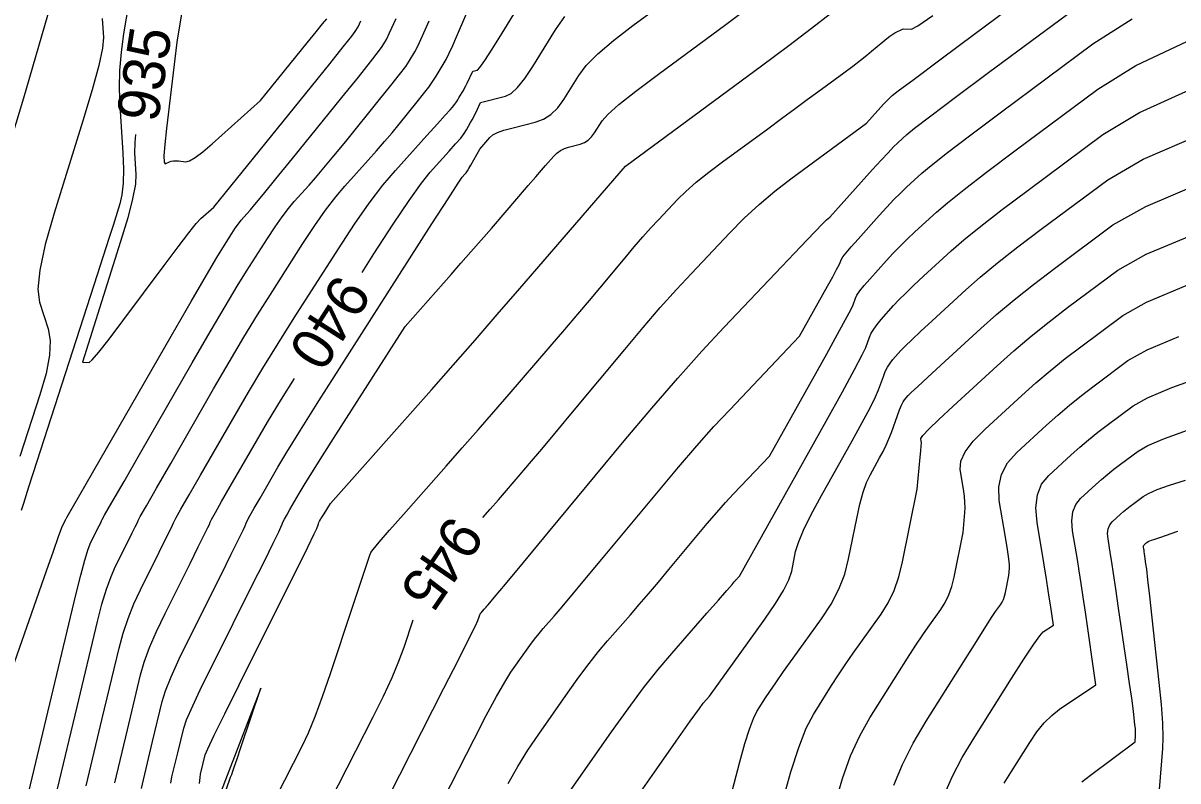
# Model space of a CAD drawing. Extents: x 2175772 to 2185556, y 721391 to 722853.
# Drawn here: x 2178671.4 to 2178748.5, y 721969.8 to 722020.4 of the extents above; entities that cross this region are included whole.
import ezdxf

# ---------------------------------------------------------------- set-up
doc = ezdxf.new("R2010")
doc.units = 0
doc.layers.add('DT_X_Contour_Major', color=7, linetype='Continuous')
doc.layers.add('DT_X_Contour_Minor', color=7, linetype='Continuous')

msp = doc.modelspace()

# ---------------------------------------------------------------- linework, layer by layer
at = {"layer": 'DT_X_Contour_Major'}
for points in [[(2178702.107, 721987.422), (2178702.598, 721987.986), (2178703.143, 721988.614), (2178704.587, 721990.287), (2178705.219, 721991.026), (2178706.032, 721991.989), (2178707.026, 721993.177), (2178708.201, 721994.588), (2178711.576, 721998.65), (2178712.803, 722000.11), (2178713.954, 722001.441), (2178715.029, 722002.644), (2178716.027, 722003.719), (2178718.586, 722006.414), (2178719.561, 722007.398), (2178720.568, 722008.328), (2178721.605, 722009.205), (2178722.674, 722010.029), (2178727.733, 722013.746), (2178728.682, 722014.804), (2178728.869, 722015.012), (2178729.025, 722015.18), (2178729.149, 722015.309), (2178729.241, 722015.399), (2178729.445, 722015.586), (2178729.849, 722015.898), (2178730.906, 722016.693), (2178732.618, 722017.97), (2178734.983, 722019.731), (2178742.163, 722025.071)], [(2178694.037, 722003.786), (2178694.831, 722005.028), (2178696.118, 722007.013), (2178697.173, 722008.58), (2178697.996, 722009.732), (2178698.588, 722010.467), (2178699.857, 722011.873), (2178700.286, 722012.357), (2178700.621, 722012.755), (2178700.863, 722013.067), (2178701.011, 722013.293), (2178701.282, 722013.78), (2178701.379, 722013.959), (2178701.469, 722014.128), (2178701.55, 722014.288), (2178701.623, 722014.438), (2178701.946, 722015.121), (2178703.609, 722015.537), (2178703.991, 722015.729), (2178704.425, 722016.127), (2178704.91, 722016.729), (2178705.446, 722017.538), (2178706.944, 722019.967), (2178707.584, 722020.873)], [(2178678.902, 722012.981), (2178678.852, 722012.463), (2178678.84, 722011.752), (2178678.931, 722010.347), (2178678.892, 722009.671), (2178678.709, 722008.695), (2178678.379, 722007.419), (2178677.905, 722005.843), (2178675.351, 721997.791), (2178675.8, 721997.773), (2178676.013, 721997.944), (2178676.46, 721998.463), (2178677.142, 721999.331), (2178678.059, 722000.548), (2178680.815, 722004.257), (2178681.742, 722005.495), (2178682.458, 722006.427), (2178682.962, 722007.053), (2178683.255, 722007.372), (2178684.125, 722008.149), (2178690.648, 722016.192), (2178691.88, 722017.714), (2178692.779, 722018.834), (2178693.347, 722019.553), (2178693.582, 722019.869), (2178693.768, 722020.177), (2178693.953, 722020.568)], [(2178709.823, 721965.097), (2178713.722, 721970.66), (2178715.012, 721972.497), (2178715.959, 721973.839), (2178716.563, 721974.685), (2178716.824, 721975.034), (2178717.238, 721975.506), (2178720.944, 721980.651), (2178721.651, 721981.678), (2178722.184, 721982.553), (2178722.544, 721983.275), (2178722.73, 721983.845), (2178722.994, 721985.164), (2178723.177, 721985.767), (2178723.526, 721986.589), (2178724.041, 721987.629), (2178724.722, 721988.887), (2178726.762, 721992.534), (2178727.446, 721993.773), (2178727.969, 721994.754), (2178728.331, 721995.478), (2178728.532, 721995.945), (2178728.852, 721996.847), (2178728.982, 721997.17), (2178729.132, 721997.465), (2178729.302, 721997.732), (2178729.492, 721997.969), (2178730.025, 721998.565), (2178730.306, 721998.857), (2178730.747, 721999.287), (2178731.35, 721999.856), (2178732.115, 722000.562), (2178734.368, 722002.631), (2178735.315, 722003.464), (2178736.469, 722004.415), (2178737.829, 722005.481), (2178739.395, 722006.664), (2178743.845, 722009.973), (2178746.198, 722011.338), (2178749.918, 722012.95)], [(2178732.973, 721969.054), (2178733.464, 721970.158), (2178734.126, 721971.404), (2178734.959, 721972.79), (2178737.409, 721976.675), (2178738.231, 721977.963), (2178738.86, 721978.91), (2178739.295, 721979.518), (2178739.537, 721979.786), (2178740.215, 721980.244), (2178740.019, 721981.591), (2178739.96, 721981.976), (2178739.869, 721982.552), (2178739.744, 721983.319), (2178739.586, 721984.278), (2178739.12, 721987.09), (2178739.038, 721988.077), (2178739.139, 721988.929), (2178739.425, 721989.647), (2178739.895, 721990.23), (2178741.393, 721991.606), (2178741.965, 721992.117), (2178742.558, 721992.619), (2178743.172, 721993.113), (2178743.807, 721993.597), (2178745.527, 721994.876), (2178746.495, 721995.422), (2178748.11, 721996.1), (2178750.372, 721996.911)], [(2178677.512, 721969.707), (2178678.361, 721973.251), (2178679.244, 721976.934), (2178679.487, 721977.781), (2178679.841, 721978.744), (2178680.303, 721979.823), (2178680.875, 721981.018), (2178682.546, 721984.359), (2178683.096, 721985.462), (2178683.494, 721986.264), (2178683.741, 721986.767), (2178683.835, 721986.969), (2178683.884, 721987.109), (2178683.982, 721987.297), (2178684.239, 721987.756), (2178684.656, 721988.487), (2178685.231, 721989.489), (2178686.977, 721992.522), (2178687.725, 721993.792), (2178688.66, 721995.325), (2178689.521, 721996.703)], [(2178691.309, 721967.314), (2178694.779, 721974.115), (2178695.466, 721975.5), (2178696.04, 721976.739), (2178696.501, 721977.833), (2178696.85, 721978.783), (2178697.455, 721980.597)]]:
    msp.add_lwpolyline(points, dxfattribs=at)
at = {"layer": 'DT_X_Contour_Minor'}
for points in [[(2178682.676, 722055.377), (2178675.464, 722029.519), (2178673.983, 722024.257), (2178672.633, 722019.554), (2178671.412, 722015.408), (2178670.32, 722011.821)], [(2178682.564, 722024.552), (2178681.66, 722019.163), (2178680.972, 722013.397), (2178680.856, 722012.323), (2178680.804, 722011.57), (2178680.816, 722011.139), (2178680.891, 722011.031), (2178681.176, 722011.169), (2178681.293, 722011.212), (2178681.43, 722011.237), (2178681.587, 722011.243), (2178681.765, 722011.231), (2178682.263, 722011.174), (2178682.514, 722011.232), (2178682.89, 722011.451), (2178683.393, 722011.829), (2178684.022, 722012.367), (2178687.253, 722015.251), (2178690.378, 722019.104), (2178690.968, 722019.834), (2178691.399, 722020.371), (2178691.671, 722020.715)], [(2178678.659, 722022.992), (2178678.107, 722019.704), (2178677.936, 722018.479), (2178677.835, 722017.269), (2178677.805, 722016.074), (2178677.846, 722014.896), (2178678.048, 722011.773), (2178678.093, 722010.68), (2178678.077, 722009.746), (2178677.998, 722008.97), (2178677.858, 722008.352), (2178677.402, 722006.913), (2178677.145, 722006.111), (2178676.118, 722002.928), (2178672.31, 721991.167), (2178671.758, 721989.455), (2178671.41, 721988.364), (2178671.264, 721987.894)], [(2178673.684, 721969.307), (2178674.999, 721974.793), (2178676.365, 721980.493), (2178676.66, 721981.64), (2178676.961, 721982.638), (2178677.266, 721983.487), (2178677.576, 721984.187), (2178678.411, 721985.855), (2178678.685, 721986.406), (2178678.884, 721986.807), (2178679.008, 721987.058), (2178679.055, 721987.159), (2178679.079, 721987.229), (2178679.222, 721987.485), (2178679.631, 721988.203), (2178680.308, 721989.382), (2178681.251, 721991.021), (2178684.122, 721996.009), (2178685.166, 721997.805), (2178686.145, 721999.453), (2178687.059, 722000.952), (2178687.908, 722002.304), (2178690.087, 722005.709), (2178690.874, 722006.907), (2178691.603, 722007.946), (2178692.272, 722008.828), (2178692.883, 722009.551), (2178694.433, 722011.268), (2178694.999, 722011.902), (2178695.532, 722012.514), (2178696.034, 722013.105), (2178696.503, 722013.675), (2178697.713, 722015.167), (2178698.132, 722015.693), (2178698.483, 722016.154), (2178698.764, 722016.548), (2178698.977, 722016.877), (2178699.452, 722017.666), (2178699.641, 722018.002), (2178699.853, 722018.421), (2178700.087, 722018.921), (2178700.344, 722019.504), (2178701.593, 722022.412)], [(2178675.598, 721969.507), (2178676.68, 721974.022), (2178677.804, 721978.713), (2178678.074, 721979.71), (2178678.401, 721980.691), (2178678.785, 721981.655), (2178679.226, 721982.602), (2178680.478, 721985.107), (2178680.891, 721985.934), (2178681.189, 721986.535), (2178681.374, 721986.912), (2178681.445, 721987.064), (2178681.482, 721987.169), (2178681.602, 721987.391), (2178681.935, 721987.98), (2178682.482, 721988.934), (2178683.241, 721990.255), (2178685.549, 721994.266), (2178686.445, 721995.798), (2178687.403, 721997.389), (2178688.421, 721999.037), (2178689.5, 722000.743), (2178692.459, 722005.369), (2178693.529, 722006.996), (2178694.518, 722008.408), (2178695.428, 722009.605), (2178696.258, 722010.588), (2178698.363, 722012.921), (2178699.062, 722013.696), (2178699.578, 722014.27), (2178699.912, 722014.645), (2178700.064, 722014.82), (2178700.225, 722015.019), (2178700.288, 722015.101), (2178700.356, 722015.198), (2178700.43, 722015.31), (2178700.508, 722015.436), (2178700.723, 722015.794), (2178700.804, 722015.933), (2178700.885, 722016.082), (2178700.967, 722016.24), (2178701.048, 722016.408), (2178701.43, 722017.213), (2178701.75, 722017.293), (2178701.903, 722017.46), (2178702.227, 722017.926), (2178702.721, 722018.692), (2178703.385, 722019.757), (2178705.383, 722022.996)], [(2178679.302, 721969.331), (2178679.425, 721969.907), (2178680.042, 721972.48), (2178680.683, 721975.155), (2178680.901, 721975.852), (2178681.281, 721976.797), (2178681.822, 721977.991), (2178682.524, 721979.434), (2178684.613, 721983.611), (2178685.301, 721984.989), (2178685.799, 721985.993), (2178686.108, 721986.621), (2178686.226, 721986.874), (2178686.287, 721987.049), (2178686.363, 721987.203), (2178686.544, 721987.533), (2178686.83, 721988.039), (2178687.221, 721988.722), (2178688.405, 721990.779), (2178689.005, 721991.785), (2178689.918, 721993.261), (2178691.144, 721995.206), (2178692.683, 721997.621), (2178697.204, 722004.688), (2178698.695, 722007.016), (2178699.78, 722008.7), (2178700.458, 722009.74), (2178700.728, 722010.136), (2178700.906, 722010.334), (2178700.981, 722010.427), (2178701.07, 722010.56), (2178701.175, 722010.731), (2178701.295, 722010.942), (2178701.891, 722012.015), (2178702.573, 722012.795), (2178702.773, 722012.959), (2178703.084, 722013.119), (2178703.503, 722013.273), (2178704.032, 722013.422), (2178705.59, 722013.812), (2178706.147, 722014.016), (2178706.653, 722014.335), (2178707.106, 722014.769), (2178707.507, 722015.319), (2178708.506, 722016.938), (2178709.013, 722017.602), (2178709.786, 722018.379), (2178710.825, 722019.268), (2178712.129, 722020.271), (2178715.961, 722023.095)], [(2178681.258, 721969.694), (2178681.339, 721970.107), (2178681.723, 721971.71), (2178682.122, 721973.375), (2178682.314, 721973.923), (2178682.72, 721974.851), (2178683.34, 721976.159), (2178684.173, 721977.849), (2178686.68, 721982.862), (2178687.507, 721984.517), (2178688.104, 721985.722), (2178688.474, 721986.476), (2178688.616, 721986.779), (2178688.69, 721986.989), (2178688.743, 721987.108), (2178688.848, 721987.309), (2178689.004, 721987.592), (2178689.211, 721987.956), (2178689.832, 721989.035), (2178690.16, 721989.584), (2178690.678, 721990.418), (2178691.385, 721991.539), (2178692.282, 721992.947), (2178696.912, 722000.183), (2178699.978, 722003.644), (2178700.639, 722004.393), (2178701.308, 722005.155), (2178701.984, 722005.932), (2178702.669, 722006.723), (2178704.506, 722008.85), (2178705.134, 722009.578), (2178705.641, 722010.164), (2178706.027, 722010.609), (2178706.292, 722010.914), (2178706.837, 722011.537), (2178707.053, 722011.751), (2178707.29, 722011.925), (2178707.549, 722012.058), (2178707.83, 722012.151), (2178708.609, 722012.346), (2178708.888, 722012.448), (2178709.14, 722012.608), (2178709.367, 722012.825), (2178709.567, 722013.1), (2178710.067, 722013.91), (2178710.442, 722014.331), (2178711.194, 722014.989), (2178712.322, 722015.882), (2178713.826, 722017.012), (2178718.34, 722020.338), (2178719.996, 722021.577)], [(2178694.346, 721965.922), (2178699.503, 721976.031), (2178700.474, 721977.938), (2178701.176, 721979.326), (2178701.609, 721980.195), (2178701.774, 721980.545), (2178701.855, 721980.788), (2178701.882, 721980.869), (2178701.901, 721980.927), (2178701.918, 721980.978), (2178701.921, 721980.988), (2178701.93, 721980.999), (2178701.952, 721981.026), (2178701.99, 721981.069), (2178702.198, 721981.304), (2178702.256, 721981.371), (2178702.314, 721981.436), (2178702.371, 721981.502), (2178702.428, 721981.567), (2178702.578, 721981.741), (2178702.865, 721982.084), (2178703.612, 721982.982), (2178704.819, 721984.434), (2178706.487, 721986.442), (2178711.55, 721992.535), (2178713.391, 721994.724), (2178715.117, 721996.721), (2178716.729, 721998.525), (2178718.226, 722000.137), (2178722.065, 722004.181), (2178723.331, 722005.512), (2178724.25, 722006.473), (2178724.822, 722007.065), (2178725.046, 722007.287), (2178725.282, 722007.461), (2178728.133, 722010.644), (2178728.697, 722011.268), (2178729.165, 722011.773), (2178729.538, 722012.161), (2178729.816, 722012.431), (2178730.43, 722012.995), (2178730.942, 722013.411), (2178732.019, 722014.237), (2178733.66, 722015.472), (2178735.866, 722017.118), (2178742.5, 722022.051)], [(2178683.17, 721969.669), (2178683.216, 721970.079), (2178683.252, 721970.306), (2178683.561, 721971.596), (2178683.728, 721971.993), (2178684.16, 721972.904), (2178684.859, 721974.328), (2178685.823, 721976.265), (2178688.748, 721982.114), (2178689.712, 721984.045), (2178690.409, 721985.45), (2178690.841, 721986.33), (2178691.006, 721986.685), (2178691.092, 721986.929), (2178691.123, 721987.014), (2178691.152, 721987.086), (2178691.178, 721987.144), (2178691.201, 721987.189), (2178691.26, 721987.292), (2178691.291, 721987.344), (2178691.408, 721987.53), (2178691.493, 721987.664), (2178691.933, 721988.351), (2178698.663, 721995.949), (2178700.114, 721997.592), (2178701.583, 721999.266), (2178703.068, 722000.972), (2178704.572, 722002.708), (2178711.628, 722010.881), (2178720.719, 722017.581), (2178722.528, 722018.926), (2178724.06, 722020.089), (2178725.315, 722021.071)], [(2178688.273, 721968.706), (2178690.054, 721972.199), (2178690.457, 721973.061), (2178690.904, 721974.152), (2178691.393, 721975.472), (2178691.926, 721977.02), (2178693.404, 721981.452), (2178693.892, 721982.914), (2178694.246, 721983.978), (2178694.468, 721984.643), (2178694.557, 721984.908), (2178694.616, 721985.086), (2178694.769, 721985.295), (2178695.185, 721985.79), (2178695.863, 721986.571), (2178696.803, 721987.638), (2178699.661, 721990.863), (2178700.726, 721992.07), (2178701.781, 721993.272), (2178702.825, 721994.469), (2178703.857, 721995.661), (2178706.595, 721998.833), (2178707.573, 721999.968), (2178708.452, 722000.997), (2178709.232, 722001.919), (2178709.914, 722002.735), (2178711.602, 722004.766), (2178712.216, 722005.495), (2178712.791, 722006.161), (2178713.328, 722006.762), (2178713.827, 722007.3), (2178715.107, 722008.648), (2178715.66, 722009.188), (2178716.359, 722009.797), (2178717.205, 722010.475), (2178718.196, 722011.223), (2178721.036, 722013.309), (2178722.049, 722014.053), (2178722.958, 722014.722), (2178723.764, 722015.315), (2178724.467, 722015.833), (2178726.203, 722017.112), (2178726.807, 722017.561), (2178727.319, 722017.95), (2178727.739, 722018.278), (2178728.065, 722018.546), (2178728.813, 722019.178), (2178729.074, 722019.393), (2178729.295, 722019.562), (2178729.476, 722019.687), (2178729.617, 722019.766), (2178730.185, 722020.031), (2178730.73, 722020.017), (2178731.144, 722020.247), (2178732.154, 722020.942)], [(2178670.506, 721976.853), (2178672.96, 721983.864), (2178673.425, 721985.188), (2178673.769, 721986.154), (2178673.991, 721986.763), (2178674.091, 721987.014), (2178674.195, 721987.207), (2178674.231, 721987.272), (2178674.259, 721987.324), (2178674.28, 721987.362), (2178674.295, 721987.387), (2178674.344, 721987.469), (2178681.287, 721999.532), (2178682.618, 722001.839), (2178683.634, 722003.59), (2178684.337, 722004.786), (2178684.725, 722005.425), (2178685.342, 722006.389), (2178685.565, 722006.728), (2178685.771, 722007.023), (2178685.961, 722007.272), (2178686.134, 722007.477), (2178686.573, 722007.963), (2178686.872, 722008.314), (2178687.44, 722009.001), (2178688.277, 722010.025), (2178689.382, 722011.386), (2178692.689, 722015.463), (2178693.787, 722016.823), (2178694.602, 722017.844), (2178695.133, 722018.527), (2178695.381, 722018.872), (2178695.662, 722019.34), (2178695.876, 722019.776), (2178696.306, 722020.733)], [(2178676.677, 722020.724), (2178676.759, 722019.461), (2178676.697, 722018.758), (2178676.447, 722017.597), (2178676.011, 722015.976), (2178675.388, 722013.897), (2178673.478, 722007.74), (2178672.879, 722005.637), (2178672.514, 722003.945), (2178672.383, 722002.664), (2178672.486, 722001.794), (2178673.074, 722000.022), (2178673.205, 721999.248), (2178673.155, 721998.254), (2178672.925, 721997.04), (2178672.515, 721995.606), (2178671.182, 721991.489)], [(2178671.771, 721969.107), (2178674.926, 721982.272), (2178675.247, 721983.569), (2178675.521, 721984.585), (2178675.747, 721985.319), (2178675.927, 721985.771), (2178676.48, 721986.878), (2178676.579, 721987.078), (2178676.641, 721987.203), (2178676.664, 721987.254), (2178676.677, 721987.288), (2178676.842, 721987.579), (2178677.327, 721988.426), (2178678.134, 721989.829), (2178679.261, 721991.788), (2178682.694, 721997.752), (2178683.886, 721999.812), (2178684.887, 722001.517), (2178685.697, 722002.868), (2178686.317, 722003.864), (2178687.714, 722006.049), (2178688.22, 722006.818), (2178688.687, 722007.485), (2178689.117, 722008.05), (2178689.509, 722008.514), (2178690.503, 722009.616), (2178690.935, 722010.108), (2178691.486, 722010.758), (2178692.155, 722011.565), (2178692.943, 722012.531), (2178695.201, 722015.315), (2178695.96, 722016.258), (2178696.542, 722016.999), (2178696.949, 722017.538), (2178697.179, 722017.874), (2178697.557, 722018.503), (2178697.759, 722018.889), (2178698.08, 722019.577), (2178698.52, 722020.566)], [(2178697.383, 721964.529), (2178701.516, 721972.631), (2178702.334, 721974.212), (2178703.018, 721975.483), (2178703.567, 721976.443), (2178703.981, 721977.093), (2178704.906, 721978.413), (2178705.243, 721978.885), (2178705.561, 721979.309), (2178705.86, 721979.687), (2178706.139, 721980.017), (2178706.857, 721980.836), (2178707.265, 721981.312), (2178707.95, 721982.126), (2178708.913, 721983.279), (2178710.153, 721984.769), (2178713.829, 721989.194), (2178715.16, 721990.778), (2178716.397, 721992.21), (2178717.539, 721993.491), (2178718.587, 721994.62), (2178723.255, 721999.536), (2178725.117, 722002.865), (2178725.47, 722003.5), (2178725.73, 722003.976), (2178725.898, 722004.295), (2178725.973, 722004.455), (2178726.05, 722004.672), (2178726.141, 722004.817), (2178726.357, 722005.089), (2178726.697, 722005.487), (2178727.162, 722006.012), (2178728.568, 722007.582), (2178729.078, 722008.141), (2178729.551, 722008.641), (2178729.989, 722009.082), (2178730.39, 722009.464), (2178731.414, 722010.404), (2178732.035, 722010.924), (2178733.131, 722011.781), (2178734.702, 722012.975), (2178736.748, 722014.504), (2178742.836, 722019.032), (2178745.464, 722020.714)], [(2178703.782, 721969.678), (2178704.428, 721970.797), (2178705.111, 721971.89), (2178705.832, 721972.957), (2178707.803, 721975.77), (2178708.522, 721976.774), (2178709.199, 721977.679), (2178709.835, 721978.484), (2178710.43, 721979.188), (2178711.96, 721980.933), (2178712.551, 721981.612), (2178713.175, 721982.341), (2178713.832, 721983.119), (2178714.523, 721983.946), (2178716.411, 721986.217), (2178717.094, 721987.03), (2178717.729, 721987.765), (2178718.315, 721988.423), (2178718.853, 721989.002), (2178721.249, 721991.526), (2178725.07, 721998.357), (2178725.794, 721999.659), (2178726.328, 722000.636), (2178726.672, 722001.289), (2178726.826, 722001.618), (2178726.984, 722002.064), (2178727.088, 722002.268), (2178727.282, 722002.548), (2178727.566, 722002.902), (2178727.939, 722003.331), (2178729.054, 722004.576), (2178729.487, 722005.046), (2178729.95, 722005.523), (2178730.443, 722006.007), (2178730.965, 722006.497), (2178732.399, 722007.813), (2178733.129, 722008.438), (2178734.244, 722009.326), (2178735.745, 722010.477), (2178737.63, 722011.891), (2178743.172, 722016.012), (2178745.709, 722017.589), (2178749.162, 722019.228)], [(2178707.682, 721968.821), (2178710.7, 721973.126), (2178711.801, 721974.664), (2178712.837, 721976.049), (2178713.811, 721977.281), (2178714.721, 721978.359), (2178717.064, 721981.031), (2178717.837, 721981.913), (2178718.4, 721982.555), (2178718.752, 721982.959), (2178718.894, 721983.123), (2178718.992, 721983.241), (2178719.028, 721983.283), (2178719.061, 721983.321), (2178719.091, 721983.355), (2178719.119, 721983.385), (2178719.243, 721983.516), (2178725.023, 721993.848), (2178726.118, 721995.817), (2178726.925, 721997.296), (2178727.446, 721998.284), (2178727.679, 721998.782), (2178727.918, 721999.455), (2178728.035, 721999.719), (2178728.207, 722000.006), (2178728.434, 722000.317), (2178728.715, 722000.65), (2178729.539, 722001.57), (2178729.896, 722001.952), (2178730.349, 722002.405), (2178730.896, 722002.931), (2178731.54, 722003.53), (2178733.383, 722005.222), (2178734.222, 722005.951), (2178735.357, 722006.87), (2178736.787, 722007.979), (2178738.513, 722009.277), (2178743.509, 722012.993), (2178745.953, 722014.463), (2178749.54, 722016.089)], [(2178717.65, 721964.912), (2178719.277, 721971.13), (2178719.609, 721972.339), (2178719.908, 721973.301), (2178720.174, 721974.015), (2178720.407, 721974.482), (2178720.985, 721975.398), (2178721.262, 721975.821), (2178721.663, 721976.403), (2178722.185, 721977.145), (2178722.831, 721978.046), (2178724.714, 721980.661), (2178725.358, 721981.647), (2178725.876, 721982.641), (2178726.268, 721983.645), (2178726.535, 721984.658), (2178727.079, 721987.371), (2178727.287, 721988.315), (2178727.505, 721989.111), (2178727.731, 721989.76), (2178727.966, 721990.262), (2178728.605, 721991.404), (2178728.833, 721991.832), (2178729.039, 721992.258), (2178729.223, 721992.684), (2178729.385, 721993.108), (2178729.786, 721994.238), (2178729.929, 721994.621), (2178730.057, 721994.924), (2178730.17, 721995.147), (2178730.268, 721995.288), (2178730.511, 721995.559), (2178730.715, 721995.762), (2178731.146, 721996.169), (2178731.804, 721996.78), (2178732.689, 721997.595), (2178735.352, 722000.04), (2178736.409, 722000.978), (2178737.582, 722001.959), (2178738.871, 722002.983), (2178740.277, 722004.051), (2178744.181, 722006.954), (2178746.379, 722008.193), (2178750.044, 722009.732)], [(2178722.117, 721968.442), (2178722.674, 721970.446), (2178723.204, 721972.085), (2178723.705, 721973.36), (2178724.177, 721974.269), (2178725.399, 721976.207), (2178725.864, 721976.931), (2178726.342, 721977.651), (2178726.834, 721978.367), (2178727.338, 721979.079), (2178728.7, 721980.97), (2178729.174, 721981.721), (2178729.571, 721982.554), (2178729.893, 721983.47), (2178730.139, 721984.468), (2178731.112, 721989.32), (2178731.319, 721991.46), (2178731.356, 721991.871), (2178731.38, 721992.184), (2178731.389, 721992.4), (2178731.384, 721992.52), (2178731.353, 721992.71), (2178731.48, 721992.898), (2178731.884, 721993.32), (2178732.565, 721993.975), (2178733.523, 721994.865), (2178736.447, 721997.55), (2178737.565, 721998.548), (2178738.722, 721999.529), (2178739.921, 722000.492), (2178741.16, 722001.437), (2178744.518, 722003.935), (2178746.408, 722005), (2178749.561, 722006.324)], [(2178725.629, 721968.325), (2178726.118, 721970), (2178726.668, 721971.513), (2178727.278, 721972.865), (2178727.948, 721974.056), (2178729.814, 721977.015), (2178730.466, 721978.041), (2178731.022, 721978.899), (2178731.482, 721979.589), (2178731.845, 721980.111), (2178732.686, 721981.279), (2178732.979, 721981.743), (2178733.224, 721982.257), (2178733.423, 721982.823), (2178733.575, 721983.439), (2178734.175, 721986.434), (2178734.303, 721987.756), (2178734.317, 721988.066), (2178734.303, 721988.43), (2178734.262, 721988.846), (2178734.194, 721989.316), (2178733.974, 721990.641), (2178734.017, 721991.181), (2178734.31, 721991.807), (2178734.853, 721992.521), (2178735.647, 721993.32), (2178738.096, 721995.569), (2178739.031, 721996.405), (2178740.001, 721997.226), (2178741.004, 721998.032), (2178742.042, 721998.824), (2178744.854, 722000.915), (2178746.437, 722001.808), (2178749.077, 722002.916)], [(2178729.562, 721969.553), (2178730.132, 721970.94), (2178730.85, 721972.37), (2178731.718, 721973.842), (2178734.229, 721977.824), (2178735.068, 721979.152), (2178735.702, 721980.147), (2178736.13, 721980.812), (2178736.353, 721981.144), (2178736.673, 721981.588), (2178736.784, 721981.765), (2178736.877, 721981.96), (2178736.953, 721982.175), (2178737.01, 721982.41), (2178737.239, 721983.549), (2178737.288, 721984.052), (2178737.278, 721984.262), (2178737.227, 721984.675), (2178737.135, 721985.292), (2178737.003, 721986.112), (2178736.596, 721988.572), (2178736.555, 721989.464), (2178736.737, 721990.295), (2178737.142, 721991.066), (2178737.771, 721991.775), (2178739.744, 721993.587), (2178740.498, 721994.261), (2178741.279, 721994.923), (2178742.088, 721995.572), (2178742.924, 721996.21), (2178745.191, 721997.896), (2178746.466, 721998.615), (2178748.594, 721999.508)], [(2178736.927, 721969.686), (2178737.358, 721970.403), (2178738.625, 721972.413), (2178739.106, 721973.116), (2178739.599, 721973.719), (2178740.103, 721974.222), (2178740.619, 721974.624), (2178743.052, 721976.269), (2178742.348, 721981.108), (2178742.201, 721982.106), (2178742.062, 721983.024), (2178741.931, 721983.863), (2178741.808, 721984.622), (2178741.49, 721986.542), (2178741.433, 721987.215), (2178741.503, 721987.797), (2178741.698, 721988.287), (2178742.018, 721988.685), (2178743.041, 721989.624), (2178743.432, 721989.973), (2178743.837, 721990.316), (2178744.256, 721990.653), (2178744.689, 721990.983), (2178745.863, 721991.857), (2178746.524, 721992.229), (2178747.627, 721992.692), (2178749.171, 721993.246)], [(2178742.099, 721969.784), (2178742.685, 721970.22), (2178745.661, 721972.445), (2178745.699, 721972.881), (2178745.702, 721972.995), (2178745.697, 721973.15), (2178745.682, 721973.346), (2178745.659, 721973.582), (2178745.583, 721974.268), (2178745.533, 721974.669), (2178745.438, 721975.36), (2178745.299, 721976.339), (2178745.116, 721977.606), (2178744.568, 721981.372), (2178744.38, 721982.655), (2178744.228, 721983.682), (2178744.111, 721984.453), (2178744.03, 721984.966), (2178743.859, 721985.993), (2178743.829, 721986.354), (2178743.866, 721986.665), (2178743.971, 721986.927), (2178744.142, 721987.14), (2178744.69, 721987.643), (2178744.899, 721987.83), (2178745.115, 721988.013), (2178745.34, 721988.193), (2178745.571, 721988.37), (2178746.2, 721988.837), (2178746.554, 721989.037), (2178747.143, 721989.285), (2178747.969, 721989.581), (2178749.032, 721989.925)], [(2178747.289, 721969.271), (2178747.528, 721972.015), (2178747.55, 721972.731), (2178747.516, 721973.705), (2178747.424, 721974.936), (2178747.275, 721976.425), (2178746.803, 721980.739), (2178746.644, 721982.177), (2178746.523, 721983.258), (2178746.44, 721983.98), (2178746.394, 721984.345), (2178746.322, 721984.839), (2178746.298, 721985.007), (2178746.278, 721985.142), (2178746.262, 721985.243), (2178746.251, 721985.31), (2178746.229, 721985.445), (2178746.225, 721985.492), (2178746.23, 721985.533), (2178746.244, 721985.567), (2178746.266, 721985.595), (2178746.338, 721985.661), (2178746.366, 721985.686), (2178746.394, 721985.71), (2178746.423, 721985.733), (2178746.454, 721985.757), (2178746.536, 721985.818), (2178746.583, 721985.844), (2178746.66, 721985.877), (2178746.768, 721985.915), (2178746.908, 721985.961), (2178747.321, 721986.09), (2178748.528, 721986.504)], [(2178683.547, 721965.152), (2178685.236, 721970.099), (2178685.33, 721970.283), (2178685.383, 721970.424), (2178685.502, 721970.768), (2178685.687, 721971.316), (2178685.938, 721972.066), (2178687.264, 721976.043), (2178685.022, 721970.197), (2178683.425, 721966.032)]]:
    msp.add_lwpolyline(points, dxfattribs=at)

# ---------------------------------------------------------------- texts
at = {"layer": 'DT_X_Contour_Major'}
for s, rotation, p in [('935', 81.15549, (2178680.385, 722013.731)), ('940', 237.48135, (2178692.388, 722003.817)), ('945', 235.72298, (2178699.982, 721987.722))]:
    msp.add_text(s, height=2.8, rotation=rotation, dxfattribs=at).set_placement(p)

doc.saveas('drawing.dxf')
